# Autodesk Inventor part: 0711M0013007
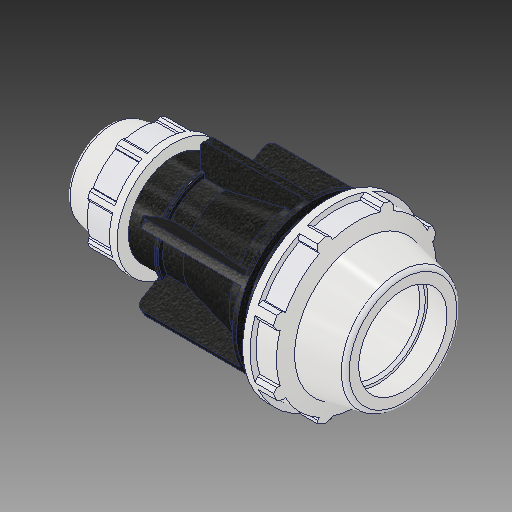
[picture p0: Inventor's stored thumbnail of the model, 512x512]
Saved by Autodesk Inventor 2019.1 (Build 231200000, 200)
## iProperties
Created: 2017-02
Part Number: 0711M0013007
Material: PVC-Piping
Description: PLASSON REDUCING COUPLER 1 1/4'' - 3/4''
Document SubType Name: Modeling
Designer: KIM
Mass: 92.6774 g
Surface Area: 199.44 cm^2
Volume: 66.1981 cm^3
Density: 1.4 g/cm^3
Appearance: PTFE
Author: KIM
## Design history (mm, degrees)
derived "0711M0.ipt"
feature "Solid1::0711M0.ipt"
tag "TaggingFeature1"
body "Solid1"
other parameters: "d_" = 42.1, "E_" = 82.042, "l_" = 54.102, "d_1" = 26.6, "E_1" = 54.102, "l_1" = 57, "d96" = 8.4397, "d2" = 42.1, "d4" = 11.66667, "d7" = 82.042, "d11" = 2, "d12" = 65.6336, "d13" = 120 deg, "d14" = 54.73, "d15" = 12 deg, "d16" = 73.8378, "d18" = 2.105, "d19" = 35 deg, "d20" = 17.5 deg, "d21" = 76.29906, "d23" = 0, "d25" = 360 deg, "d27" = 1.64084, "d42" = 15.4, "d46" = 1.263, "d52" = 48.27586, "d53" = 12 deg, "d54" = 54.102, "d56" = 39.9, "d57" = 26.6, "d58" = 37.89, "d59" = 23.94, "d60" = 48.6918, "d61" = 43.2816, "d62" = 14, "d63" = 16.8, "d64" = 120 deg, "d65" = 54.102, "d74" = 50.31486, "d75" = 35 deg, "d76" = 17.5 deg, "d78" = 0, "d80" = 360 deg, "d85" = 1.08204, "d88" = 0.532, "d93" = 57, "d94" = 57.4294, "d97" = 2.81323, "d98" = 3.6068, "d99" = 0, "d100" = 3.28168, "d102" = 360 deg, "d104" = 2, "d106" = 0, "d107" = 3.6068, "d108" = 0, "d109" = 3.6068, "d110" = 0
